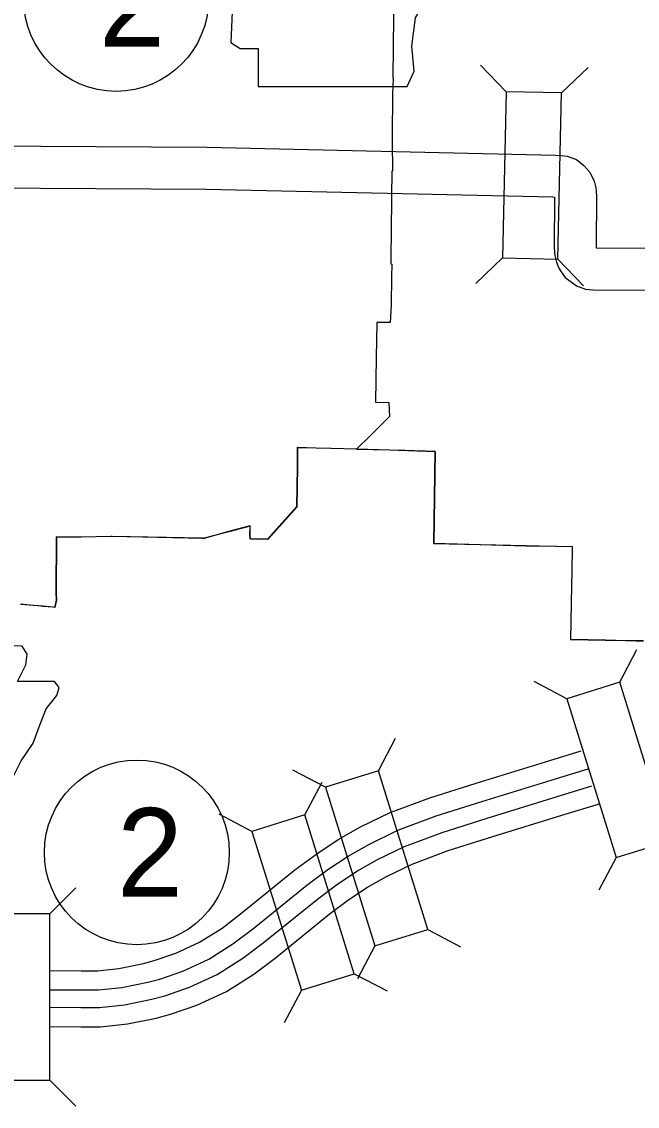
# Model space of a CAD drawing. Extents: x 670147 to 673275, y 705573 to 707613.
# Drawn here: x 670400.2 to 670466.2, y 707053.1 to 707169.4 of the extents above; entities that cross this region are included whole.
import ezdxf

# ---------------------------------------------------------------- set-up
doc = ezdxf.new("R2010")
doc.units = 0
for name, color, linetype in [('10', 7, 'Continuous'), ('20', 7, 'Continuous'), ('21', 7, 'Continuous'), ('27', 7, 'Continuous'), ('6', 7, 'Continuous')]:
    doc.layers.add(name, color=color, linetype=linetype)

msp = doc.modelspace()

# ---------------------------------------------------------------- linework, layer by layer
at = {"layer": '10'}
for points in [[(670371.15, 707156.06), (670371.44, 707156.06), (670384.49, 707156.14), (670420.06, 707155.92), (670457.42, 707155.09), (670458.06, 707155.03), (670458.68, 707154.95), (670459.68, 707154.62), (670460.47, 707153.97), (670461.12, 707153.24), (670461.56, 707152.29), (670461.76, 707151.56), (670461.82, 707150.72), (670461.78, 707145.34), (670461.79, 707145.14), (670469.66, 707145.1), (670499.35, 707144.65), (670523.91, 707143.95), (670538.58, 707143.54), (670546, 707143.36)], [(670371.49, 707151.56), (670384.49, 707151.64), (670419.99, 707151.42), (670457.13, 707150.6), (670457.32, 707150.58), (670457.28, 707145.16), (670457.35, 707144.32), (670457.52, 707143.61), (670457.77, 707142.97), (670458.03, 707142.58), (670458.45, 707141.97), (670459.12, 707141.5), (670459.67, 707141.08), (670460.65, 707140.73), (670461.44, 707140.64), (670469.62, 707140.6), (670499.26, 707140.15), (670523.79, 707139.45), (670538.46, 707139.04), (670546, 707138.86)], [(670403.24, 707067.69), (670406.6, 707067.67), (670408.35, 707067.67), (670410.65, 707067.91), (670413.28, 707068.44), (670414.44, 707068.75), (670416.75, 707069.55), (670419.3, 707070.74), (670421.7, 707072.24), (670423.68, 707073.75), (670429.51, 707078.47), (670431.86, 707080.21), (670434.13, 707081.72), (670436.53, 707083.08), (670439.72, 707084.61), (670443.98, 707086.21), (670448.92, 707087.78), (670456.34, 707090.07), (670460.16, 707091.23)], [(670403.24, 707065.63), (670406.6, 707065.61), (670408.46, 707065.61), (670410.96, 707065.87), (670413.75, 707066.43), (670415.05, 707066.78), (670417.52, 707067.63), (670420.29, 707068.92), (670422.87, 707070.54), (670424.95, 707072.13), (670430.77, 707076.84), (670433.04, 707078.52), (670435.21, 707079.96), (670437.49, 707081.25), (670440.53, 707082.72), (670444.65, 707084.26), (670449.53, 707085.81), (670456.95, 707088.09), (670460.94, 707089.31)], [(670403.24, 707063.75), (670406.59, 707063.73), (670408.56, 707063.74), (670411.25, 707064.01), (670414.18, 707064.61), (670415.59, 707064.98), (670418.23, 707065.89), (670421.18, 707067.27), (670423.94, 707069), (670426.11, 707070.65), (670431.92, 707075.35), (670434.12, 707076.98), (670436.2, 707078.36), (670438.36, 707079.59), (670441.26, 707080.99), (670445.27, 707082.49), (670450.09, 707084.03), (670457.49, 707086.3), (670461.32, 707087.47)], [(670403.27, 707061.69), (670406.59, 707061.67), (670408.67, 707061.67), (670411.56, 707061.97), (670414.65, 707062.6), (670416.19, 707063.01), (670419, 707063.98), (670422.17, 707065.46), (670425.11, 707067.3), (670427.38, 707069.03), (670433.18, 707073.72), (670435.3, 707075.29), (670437.28, 707076.61), (670439.32, 707077.76), (670442.08, 707079.09), (670445.94, 707080.54), (670450.71, 707082.06), (670458.1, 707084.33), (670462.13, 707085.56)]]:
    msp.add_lwpolyline(points, dxfattribs=at)
at = {"layer": '20'}
for p, q in [((670452.14, 707161.87), (670449.4, 707164.73)), ((670458.08, 707161.74), (670460.94, 707164.48)), ((670451.75, 707144.06), (670448.88, 707141.32)), ((670457.68, 707143.93), (670460.42, 707141.06)), ((670464.31, 707098.58), (670466.15, 707102.09)), ((670458.64, 707096.82), (670455.13, 707098.66)), ((670438.45, 707089.1), (670440.29, 707092.6)), ((670432.78, 707087.33), (670429.27, 707089.18)), ((670430.59, 707084.36), (670432.43, 707087.86)), ((670424.91, 707082.59), (670421.41, 707084.44)), ((670463.93, 707079.8), (670462.08, 707076.3)), ((670403.25, 707073.76), (670406.05, 707076.56)), ((670443.74, 707072.08), (670447.24, 707070.24)), ((670438.06, 707070.32), (670436.22, 707066.81)), ((670435.87, 707067.34), (670439.38, 707065.5)), ((670430.2, 707065.58), (670428.36, 707062.07)), ((670403.24, 707055.94), (670406.04, 707053.14))]:
    msp.add_line(p, q, dxfattribs=at)
for points in [[(670457.68, 707143.93), (670458.08, 707161.74), (670452.14, 707161.87), (670451.75, 707144.06)], [(670458.64, 707096.82), (670463.93, 707079.8), (670469.6, 707081.56), (670464.31, 707098.58)], [(670432.78, 707087.33), (670438.06, 707070.32), (670443.74, 707072.08), (670438.45, 707089.1)], [(670424.91, 707082.59), (670430.2, 707065.58), (670435.87, 707067.34), (670430.59, 707084.36)], [(670397.31, 707073.76), (670397.3, 707055.94), (670403.24, 707055.94), (670403.25, 707073.76)]]:
    msp.add_lwpolyline(points, close=True, dxfattribs=at)
at = {"layer": '21'}
for points in [[(670422, 707186.3), (670423.14, 707178.68), (670422.64, 707167.14), (670423.65, 707166.5), (670425.56, 707166.5), (670425.56, 707162.44), (670441.54, 707162.44), (670442.3, 707164.09), (670442.05, 707166.76), (670442.43, 707169.8), (670443.83, 707172.21), (670444.71, 707173.99), (670445.98, 707175.89), (670446.74, 707177.92), (670447.38, 707179.57), (670448.52, 707180.97), (670448.78, 707181.86), (670448.27, 707182.49), (670444.33, 707182.49), (670445.22, 707184.27), (670445.35, 707185.41), (670444.82, 707186.29)], [(670377.48, 707102.48), (670378.62, 707094.86), (670378.11, 707083.32), (670379.13, 707082.68), (670381.03, 707082.68), (670381.03, 707078.62), (670397.02, 707078.62), (670397.78, 707080.27), (670397.52, 707082.94), (670397.9, 707085.98), (670399.3, 707088.39), (670400.19, 707090.17), (670401.46, 707092.07), (670402.22, 707094.1), (670402.85, 707095.75), (670403.99, 707097.15), (670404.25, 707098.04), (670403.74, 707098.67), (670399.81, 707098.67), (670400.7, 707100.45), (670400.82, 707101.59), (670400.3, 707102.47)]]:
    msp.add_lwpolyline(points, close=True, dxfattribs=at)
at = {"layer": '27'}
for centre in [(670410.36, 707171.81), (670412.58, 707080.35)]:
    msp.add_circle(centre, 9.9, dxfattribs=at)
at = {"layer": '6'}
for points in [[(670440.09, 707173.19), (670440.01, 707163.4), (670440.02, 707163.28), (670439.98, 707161.59), (670439.95, 707159.94), (670439.94, 707158.74), (670439.94, 707157.52), (670439.94, 707156.3), (670439.95, 707153.62), (670439.95, 707153.49), (670439.95, 707153.35), (670439.91, 707153.35), (670439.87, 707150.61), (670439.85, 707149.54), (670439.83, 707147.87), (670439.83, 707147.76), (670439.77, 707143.42), (670439.88, 707143.41), (670439.88, 707143.37), (670439.88, 707143.22), (670439.87, 707142.2), (670439.87, 707142.03), (670439.83, 707139.04), (670439.72, 707137.14), (670438.27, 707137.14), (670438.21, 707133.4), (670438.16, 707128.62), (670439.58, 707128.58), (670439.64, 707127.07), (670437.59, 707124.99), (670436.12, 707123.57), (670433.35, 707123.64), (670431.77, 707123.68), (670429.76, 707123.73), (670429.74, 707121.77), (670429.74, 707121.7), (670429.72, 707119.51), (670429.69, 707117.37), (670426.59, 707113.91), (670424.73, 707113.94), (670424.68, 707114.41), (670424.7, 707115.35), (670422.53, 707114.76), (670419.63, 707113.97), (670419.63, 707114.02), (670409.9, 707114.21), (670409.78, 707114.21), (670406.61, 707114.15), (670406.18, 707114.13), (670405.56, 707114.14), (670404.93, 707114.15), (670404.3, 707114.15), (670403.95, 707114.17), (670403.91, 707108.19), (670403.94, 707107.4), (670403.77, 707106.6), (670403.58, 707106.63), (670402.5, 707106.73)], [(670440.09, 707173.19), (670440.01, 707163.4), (670440.02, 707163.28), (670439.98, 707161.59), (670439.95, 707159.94), (670439.94, 707158.74), (670439.94, 707157.52), (670439.94, 707156.3), (670439.95, 707153.62), (670439.95, 707153.49), (670439.95, 707153.35), (670439.91, 707153.35), (670439.87, 707150.61), (670439.85, 707149.54), (670439.83, 707147.87), (670439.83, 707147.76), (670439.77, 707143.42), (670439.88, 707143.41), (670439.88, 707143.37), (670439.88, 707143.22), (670439.87, 707142.2), (670439.87, 707142.03), (670439.83, 707139.04), (670439.72, 707137.14), (670438.27, 707137.14), (670438.21, 707133.4), (670438.16, 707128.62), (670439.58, 707128.58), (670439.64, 707127.07), (670437.59, 707124.99), (670436.12, 707123.57)], [(670466.87, 707103.01), (670466.11, 707103.02), (670465.12, 707103.04), (670465, 707103.04), (670462.79, 707103.09), (670459.08, 707103.17), (670459.14, 707106.98), (670459.18, 707109.03), (670459.2, 707110.35), (670459.24, 707113.11), (670455.68, 707113.18), (670454.29, 707113.2), (670449.39, 707113.33), (670444.41, 707113.45), (670444.55, 707123.32), (670441.29, 707123.41), (670439.66, 707123.46), (670436.16, 707123.55), (670436.16, 707123.55), (670433.38, 707123.62), (670431.8, 707123.66), (670429.79, 707123.71), (670429.77, 707121.75), (670429.77, 707121.68), (670429.75, 707119.49), (670429.72, 707117.35), (670426.62, 707113.89), (670424.76, 707113.92), (670424.71, 707114.39), (670424.73, 707115.33), (670422.56, 707114.74), (670419.66, 707113.98), (670409.93, 707114.2), (670409.81, 707114.19), (670406.65, 707114.13), (670406.21, 707114.12), (670405.59, 707114.12), (670404.96, 707114.13), (670404.33, 707114.14), (670403.98, 707114.15), (670403.94, 707108.18), (670403.97, 707107.38), (670403.8, 707106.58), (670403.61, 707106.62), (670402.5, 707106.72), (670402.03, 707106.76), (670401.49, 707106.8), (670400.16, 707106.93)], [(670436.12, 707123.57), (670439.63, 707123.48)], [(670439.63, 707123.48), (670444.52, 707123.33)], [(670444.52, 707123.33), (670444.38, 707113.47)], [(670444.38, 707113.47), (670449.36, 707113.35)], [(670449.36, 707113.35), (670454.26, 707113.22)], [(670454.26, 707113.22), (670455.65, 707113.19)], [(670455.65, 707113.19), (670459.21, 707113.12)], [(670459.21, 707113.12), (670459.17, 707110.37)], [(670459.17, 707110.37), (670459.14, 707109.05)], [(670459.14, 707109.05), (670459.11, 707107)], [(670402.5, 707106.73), (670402.43, 707106.73), (670402, 707106.77), (670401.46, 707106.82), (670400.13, 707106.94)], [(670459.11, 707107), (670459.05, 707103.18)], [(670459.05, 707103.18), (670462.76, 707103.11)], [(670462.76, 707103.11), (670464.97, 707103.06)], [(670464.97, 707103.06), (670465.08, 707103.06)], [(670465.08, 707103.06), (670466.08, 707103.04)], [(670466.08, 707103.04), (670466.83, 707103.02)]]:
    msp.add_lwpolyline(points, dxfattribs=at)

# ---------------------------------------------------------------- texts
at = {"layer": '27'}
for p in [(670408.51, 707166.71), (670410.45, 707075.6)]:
    msp.add_text('2', height=9.5, dxfattribs=at).set_placement(p)

doc.saveas('drawing.dxf')
